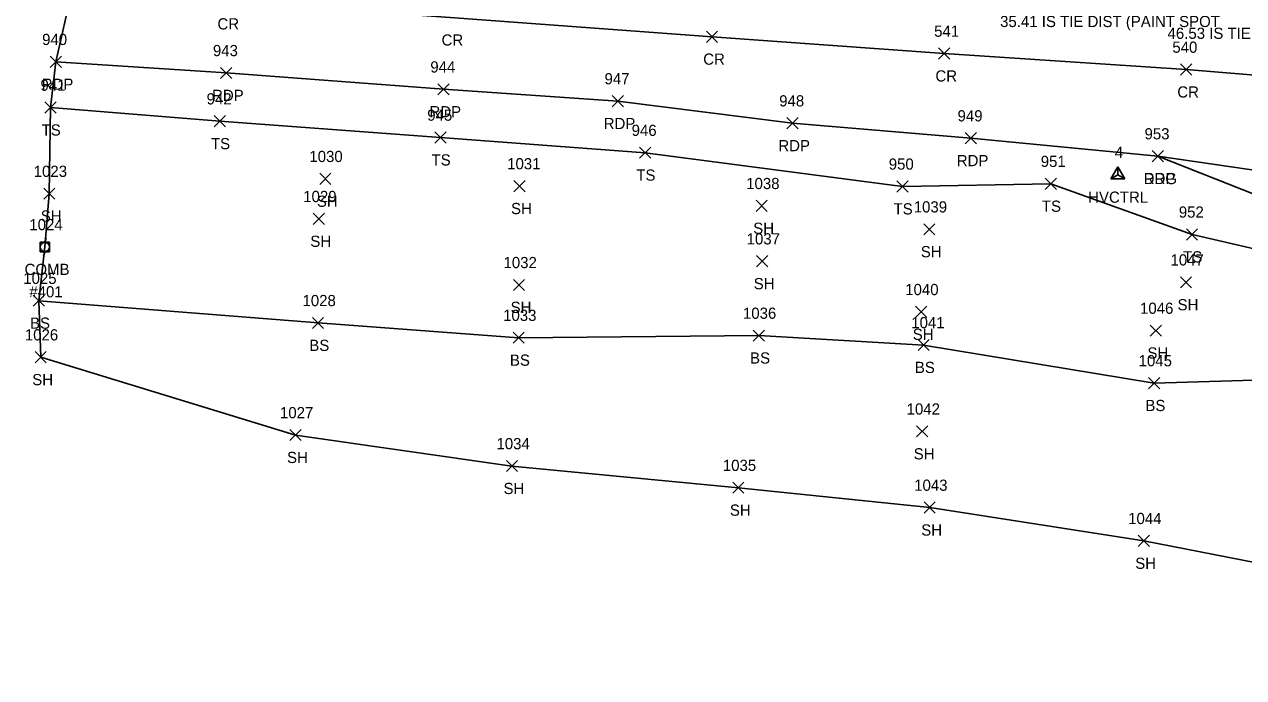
# Model space of a CAD drawing. Extents: x 1679360 to 1685861, y 903420 to 905946.
# Drawn here: x 1679458.8 to 1679676.5, y 903931.8 to 904048.5 of the extents above; entities that cross this region are included whole.
import ezdxf

# ---------------------------------------------------------------- set-up
doc = ezdxf.new("R2010")
doc.units = 0
for name, color, linetype in [('C_A', 7, 'Continuous'), ('C_C', 7, 'Continuous'), ('C_I', 7, 'Continuous'), ('CPSM', 7, 'Continuous'), ('L_A', 7, 'Continuous'), ('L_I', 7, 'Continuous'), ('L_TIC', 7, 'Continuous'), ('LELB', 7, 'Continuous'), ('LSOGP', 7, 'Continuous'), ('P_A', 7, 'Continuous'), ('P_I', 7, 'Continuous'), ('P_TIC', 7, 'Continuous'), ('PET', 7, 'Continuous'), ('PRC', 7, 'Continuous'), ('R_A', 7, 'Continuous'), ('R_I', 7, 'Continuous'), ('R_TIC', 7, 'Continuous'), ('RDG', 7, 'Continuous'), ('U_A', 7, 'Continuous'), ('U_C', 7, 'Continuous'), ('U_I', 7, 'Continuous'), ('UP', 7, 'Continuous')]:
    doc.layers.add(name, color=color, linetype=linetype)

msp = doc.modelspace()

# ---------------------------------------------------------------- linework, layer by layer
at = {"layer": 'CPSM'}
for p, q in [((1679652.8, 904020.88), (1679654.05, 904023.04)), ((1679652.8, 904020.88), (1679654.05, 904021.6)), ((1679655.3, 904020.88), (1679654.05, 904023.04)), ((1679654.05, 904021.6), (1679654.05, 904023.04)), ((1679654.05, 904021.6), (1679654.05, 904021.6)), ((1679654.05, 904021.6), (1679655.3, 904020.88)), ((1679652.8, 904020.88), (1679655.3, 904020.88))]:
    msp.add_line(p, q, dxfattribs=at)
at = {"layer": 'L_TIC'}
for points in [[(1679462.5, 904032.6), (1679464.5, 904034.6)], [(1679464.5, 904032.6), (1679462.5, 904034.6)], [(1679492.73, 904030.16), (1679494.73, 904032.16)], [(1679494.73, 904030.16), (1679492.73, 904032.16)], [(1679532.11, 904027.25), (1679534.11, 904029.25)], [(1679534.11, 904027.25), (1679532.11, 904029.25)], [(1679568.66, 904024.54), (1679570.66, 904026.54)], [(1679570.66, 904024.54), (1679568.66, 904026.54)], [(1679511.56, 904019.87), (1679513.56, 904021.87)], [(1679513.56, 904019.87), (1679511.56, 904021.87)], [(1679462.28, 904017.22), (1679464.28, 904019.22)], [(1679464.28, 904017.22), (1679462.28, 904019.22)], [(1679546.22, 904018.57), (1679548.22, 904020.57)], [(1679548.22, 904018.57), (1679546.22, 904020.57)], [(1679614.59, 904018.51), (1679616.59, 904020.51)], [(1679616.59, 904018.51), (1679614.59, 904020.51)], [(1679641.06, 904018.99), (1679643.06, 904020.99)], [(1679643.06, 904018.99), (1679641.06, 904020.99)], [(1679589.46, 904015.04), (1679591.46, 904017.04)], [(1679591.46, 904015.04), (1679589.46, 904017.04)], [(1679510.39, 904012.72), (1679512.39, 904014.72)], [(1679512.39, 904012.72), (1679510.39, 904014.72)], [(1679619.38, 904010.86), (1679621.38, 904012.86)], [(1679621.38, 904010.86), (1679619.38, 904012.86)], [(1679666.28, 904009.94), (1679668.28, 904011.94)], [(1679668.28, 904009.94), (1679666.28, 904011.94)], [(1679589.54, 904005.15), (1679591.54, 904007.15)], [(1679591.54, 904005.15), (1679589.54, 904007.15)], [(1679546.14, 904000.92), (1679548.14, 904002.92)], [(1679548.14, 904000.92), (1679546.14, 904002.92)], [(1679665.21, 904001.39), (1679667.21, 904003.39)], [(1679667.21, 904001.39), (1679665.21, 904003.39)], [(1679460.4, 903998.1), (1679462.4, 904000.1)], [(1679462.4, 903998.1), (1679460.4, 904000.1)], [(1679617.93, 903996.1), (1679619.93, 903998.1)], [(1679619.93, 903996.1), (1679617.93, 903998.1)], [(1679510.25, 903994.13), (1679512.25, 903996.13)], [(1679512.25, 903994.13), (1679510.25, 903996.13)], [(1679546.07, 903991.49), (1679548.07, 903993.49)], [(1679548.07, 903991.49), (1679546.07, 903993.49)], [(1679588.93, 903991.87), (1679590.93, 903993.87)], [(1679590.93, 903991.87), (1679588.93, 903993.87)], [(1679659.83, 903992.76), (1679661.83, 903994.76)], [(1679661.83, 903992.76), (1679659.83, 903994.76)], [(1679618.36, 903990.19), (1679620.36, 903992.19)], [(1679620.36, 903990.19), (1679618.36, 903992.19)], [(1679460.75, 903988.01), (1679462.75, 903990.01)], [(1679462.75, 903988.01), (1679460.75, 903990.01)], [(1679659.51, 903983.39), (1679661.51, 903985.39)], [(1679661.51, 903983.39), (1679659.51, 903985.39)], [(1679506.23, 903974.11), (1679508.23, 903976.11)], [(1679508.23, 903974.11), (1679506.23, 903976.11)], [(1679618.1, 903974.76), (1679620.1, 903976.76)], [(1679620.1, 903974.76), (1679618.1, 903976.76)], [(1679544.88, 903968.57), (1679546.88, 903970.57)], [(1679546.88, 903968.57), (1679544.88, 903970.57)], [(1679585.29, 903964.7), (1679587.29, 903966.7)], [(1679587.29, 903964.7), (1679585.29, 903966.7)], [(1679619.45, 903961.15), (1679621.45, 903963.15)], [(1679621.45, 903961.15), (1679619.45, 903963.15)], [(1679657.66, 903955.21), (1679659.66, 903957.21)], [(1679659.66, 903955.21), (1679657.66, 903957.21)]]:
    msp.add_lwpolyline(points, dxfattribs=at)
at = {"layer": 'LELB'}
for points in [[(1679463.5, 904033.6), (1679493.73, 904031.16), (1679533.11, 904028.25), (1679569.66, 904025.54), (1679615.59, 904019.51), (1679642.06, 904019.99), (1679667.28, 904010.94), (1679690.23, 904005.6), (1679704.94, 903987.11), (1679728.07, 903978.5), (1679734.09, 903971.49), (1679734.69, 903963.98), (1679734.78, 903951.98), (1679729.23, 903943.97)], [(1679461.4, 903999.1), (1679511.25, 903995.13), (1679547.07, 903992.49), (1679589.93, 903992.87), (1679619.36, 903991.19), (1679660.51, 903984.39), (1679682.29, 903985.04), (1679699.78, 903975.77), (1679714.27, 903970.83), (1679728.59, 903970.78), (1679728.89, 903969.37), (1679727.12, 903965.2), (1679730.26, 903954.68), (1679724.72, 903944.32)]]:
    msp.add_lwpolyline(points, dxfattribs=at)
at = {"layer": 'LSOGP'}
msp.add_lwpolyline([(1679467.34, 904054.68), (1679464.45, 904041.77), (1679463.5, 904033.6), (1679463.28, 904018.22), (1679462.49, 904008.7), (1679461.4, 903999.1), (1679461.75, 903989.01), (1679507.23, 903975.11), (1679545.88, 903969.57), (1679586.29, 903965.7), (1679620.45, 903962.15), (1679658.66, 903956.21), (1679681.25, 903951.79)], dxfattribs=at)
at = {"layer": 'P_TIC'}
for points in [[(1679580.59, 904045.25), (1679582.59, 904047.25)], [(1679582.59, 904045.25), (1679580.59, 904047.25)], [(1679622.03, 904042.25), (1679624.03, 904044.25)], [(1679624.03, 904042.25), (1679622.03, 904044.25)], [(1679463.45, 904040.77), (1679465.45, 904042.77)], [(1679465.45, 904040.77), (1679463.45, 904042.77)], [(1679665.22, 904039.39), (1679667.22, 904041.39)], [(1679667.22, 904039.39), (1679665.22, 904041.39)], [(1679493.85, 904038.78), (1679495.85, 904040.78)], [(1679495.85, 904038.78), (1679493.85, 904040.78)], [(1679532.66, 904035.86), (1679534.66, 904037.86)], [(1679534.66, 904035.86), (1679532.66, 904037.86)], [(1679563.76, 904033.75), (1679565.76, 904035.75)], [(1679565.76, 904033.75), (1679563.76, 904035.75)], [(1679594.94, 904029.8), (1679596.94, 904031.8)], [(1679596.94, 904029.8), (1679594.94, 904031.8)], [(1679626.79, 904027.13), (1679628.79, 904029.13)], [(1679628.79, 904027.13), (1679626.79, 904029.13)], [(1679660.16, 904023.92), (1679662.16, 904025.92)], [(1679662.16, 904023.92), (1679660.16, 904025.92)]]:
    msp.add_lwpolyline(points, dxfattribs=at)
at = {"layer": 'PET'}
msp.add_lwpolyline([(1679464.45, 904041.77), (1679494.85, 904039.78), (1679533.66, 904036.86), (1679564.76, 904034.75), (1679595.94, 904030.8), (1679627.79, 904028.13), (1679661.16, 904024.92), (1679697.2, 904019.69), (1679719.42, 904015.4), (1679737.48, 904014.62), (1679744.58, 904019.77), (1679770.86, 904017.76), (1679789.63, 904016.53)], dxfattribs=at)
at = {"layer": 'PRC'}
msp.add_lwpolyline([(1680209.65, 904002.04), (1680152.97, 904005.78), (1680100.29, 904009.57), (1680049.21, 904012.91), (1679999.46, 904016.39), (1679940.5, 904020.99), (1679893.64, 904024.04), (1679847.03, 904027.44), (1679827.53, 904028.69), (1679808.61, 904029.86), (1679757.07, 904033.5), (1679707.39, 904036.98), (1679666.22, 904040.39), (1679623.03, 904043.25), (1679581.59, 904046.25), (1679534.87, 904049.67), (1679494.87, 904052.55), (1679467.34, 904054.68)], dxfattribs=at)
at = {"layer": 'R_TIC'}
for points in [[(1679660.16, 904023.92), (1679662.16, 904025.92)], [(1679662.16, 904023.92), (1679660.16, 904025.92)]]:
    msp.add_lwpolyline(points, dxfattribs=at)
at = {"layer": 'RDG'}
msp.add_lwpolyline([(1679661.16, 904024.92), (1679683.89, 904015.94), (1679697.93, 904008.67), (1679719.81, 903993.91), (1679739.61, 903978.84), (1679766.51, 903961.28), (1679785.72, 903950.36), (1679809.97, 903931.78)], dxfattribs=at)
at = {"layer": 'UP'}
for p, q in [((1679461.65, 904007.86), (1679461.65, 904009.53)), ((1679461.65, 904009.53), (1679463.32, 904009.53)), ((1679462.74, 904010.36), (1679462.49, 904009.53)), ((1679462.49, 904008.7), (1679462.49, 904008.7)), ((1679463.32, 904009.53), (1679463.32, 904007.86)), ((1679463.32, 904007.86), (1679461.65, 904007.86)), ((1679462.24, 904007.03), (1679462.49, 904007.86))]:
    msp.add_line(p, q, dxfattribs=at)
msp.add_circle((1679462.49, 904008.7), 0.833, dxfattribs=at)

# ---------------------------------------------------------------- texts
at = {"layer": 'C_A'}
msp.add_text('HVCTRL', height=2, dxfattribs=at).set_placement((1679648.74, 904016.6))
at = {"layer": 'C_C'}
for s, p in [('35.41 IS TIE DIST (PAINT SPOT', (1679633.02, 904047.98)), ('46.53 IS TIE DIST (PAINT SPOT', (1679662.91, 904045.87))]:
    msp.add_text(s, height=2, dxfattribs=at).set_placement(p)
at = {"layer": 'C_I'}
msp.add_text('4', height=2, dxfattribs=at).set_placement((1679653.48, 904024.6))
at = {"layer": 'L_A'}
for s, p in [('TS', (1679461.91, 904028.6)), ('TS', (1679492.14, 904026.16)), ('TS', (1679531.52, 904023.25)), ('TS', (1679568.07, 904020.54)), ('SH', (1679511.05, 904015.87)), ('TS', (1679640.47, 904014.99)), ('SH', (1679461.76, 904013.22)), ('SH', (1679545.71, 904014.57)), ('TS', (1679614, 904014.51)), ('SH', (1679588.95, 904011.04)), ('SH', (1679509.88, 904008.72)), ('SH', (1679618.86, 904006.86)), ('TS', (1679665.69, 904005.94)), ('SH', (1679589.03, 904001.15)), ('SH', (1679545.63, 903996.92)), ('SH', (1679664.7, 903997.39)), ('BS', (1679459.84, 903994.1)), ('SH', (1679617.42, 903992.1)), ('BS', (1679509.7, 903990.13)), ('BS', (1679545.51, 903987.49)), ('BS', (1679588.38, 903987.87)), ('SH', (1679659.32, 903988.76)), ('BS', (1679617.8, 903986.19)), ('SH', (1679460.24, 903984.01)), ('BS', (1679658.95, 903979.39)), ('SH', (1679505.72, 903970.11)), ('SH', (1679617.59, 903970.76)), ('SH', (1679544.37, 903964.57)), ('SH', (1679584.78, 903960.7)), ('SH', (1679618.94, 903957.15)), ('SH', (1679657.14, 903951.21))]:
    msp.add_text(s, height=2, dxfattribs=at).set_placement(p)
at = {"layer": 'L_I'}
for s, p in [('941', (1679461.7, 904036.6)), ('942', (1679491.37, 904034.16)), ('945', (1679530.75, 904031.25)), ('946', (1679567.24, 904028.54)), ('1030', (1679509.71, 904023.87)), ('1031', (1679545.02, 904022.57)), ('950', (1679613.14, 904022.51)), ('951', (1679640.27, 904022.99)), ('1023', (1679460.5, 904021.22)), ('1038', (1679587.69, 904019.04)), ('1029', (1679508.61, 904016.72)), ('1039', (1679617.6, 904014.86)), ('952', (1679664.92, 904013.94)), ('1037', (1679587.77, 904009.15)), ('1032', (1679544.37, 904004.92)), ('1047', (1679663.44, 904005.39)), ('1025', (1679458.63, 904002.1)), ('1040', (1679616.08, 904000.1)), ('1028', (1679508.48, 903998.13)), ('1033', (1679544.3, 903995.49)), ('1036', (1679587.11, 903995.87)), ('1046', (1679658, 903996.76)), ('1041', (1679617.16, 903994.19)), ('1026', (1679458.92, 903992.01)), ('1045', (1679657.74, 903987.39)), ('1027', (1679504.46, 903978.11)), ('1042', (1679616.33, 903978.76)), ('1034', (1679543.11, 903972.57)), ('1035', (1679583.52, 903968.7)), ('1043', (1679617.68, 903965.15)), ('1044', (1679655.88, 903959.21))]:
    msp.add_text(s, height=2, dxfattribs=at).set_placement(p)
at = {"layer": 'P_A'}
for s, p in [('CR', (1679493.3, 904047.55)), ('CR', (1679533.31, 904044.67)), ('CR', (1679580.02, 904041.25)), ('RDP', (1679461.93, 904036.77)), ('CR', (1679621.47, 904038.25)), ('RDP', (1679492.34, 904034.78)), ('CR', (1679664.65, 904035.39)), ('RDP', (1679531.15, 904031.86)), ('RDP', (1679562.25, 904029.75)), ('RDP', (1679593.43, 904025.8)), ('RDP', (1679625.28, 904023.13)), ('RDP', (1679658.65, 904019.92))]:
    msp.add_text(s, height=2, dxfattribs=at).set_placement(p)
at = {"layer": 'P_I'}
for s, p in [('541', (1679621.24, 904046.25)), ('940', (1679462, 904044.77)), ('540', (1679663.77, 904043.39)), ('943', (1679492.49, 904042.78)), ('944', (1679531.3, 904039.86)), ('947', (1679562.4, 904037.75)), ('948', (1679593.58, 904033.8)), ('949', (1679625.42, 904031.13)), ('953', (1679658.8, 904027.92))]:
    msp.add_text(s, height=2, dxfattribs=at).set_placement(p)
at = {"layer": 'R_A'}
msp.add_text('DRG', height=2, dxfattribs=at).set_placement((1679658.65, 904019.92))
at = {"layer": 'R_I'}
msp.add_text('953', height=2, dxfattribs=at).set_placement((1679658.8, 904027.92))
at = {"layer": 'U_A'}
msp.add_text('COMB', height=2, dxfattribs=at).set_placement((1679458.87, 904003.7))
at = {"layer": 'U_C'}
msp.add_text('#401', height=2, dxfattribs=at).set_placement((1679459.72, 903999.7))
at = {"layer": 'U_I'}
msp.add_text('1024', height=2, dxfattribs=at).set_placement((1679459.72, 904011.7))

doc.saveas('drawing.dxf')
